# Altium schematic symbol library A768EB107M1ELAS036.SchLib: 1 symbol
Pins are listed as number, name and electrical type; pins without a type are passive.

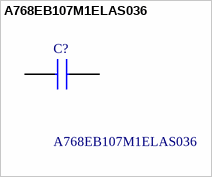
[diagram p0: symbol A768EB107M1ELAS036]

## A768EB107M1ELAS036
designator C?
A768, Aluminum, Polymer Aluminum, 100 uF, 20%, 25 VDC, -55/+125C, 125C, -55C, 125C, 2,000 Hrs, 36 mOhms, 500 uA, 6.3mm, 5.7mm, 1000; Manufacturer_Name: KEMET; Geometry.Height: 6mm
footprint CAPAE660X600N
pins: 1 +, 2 -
